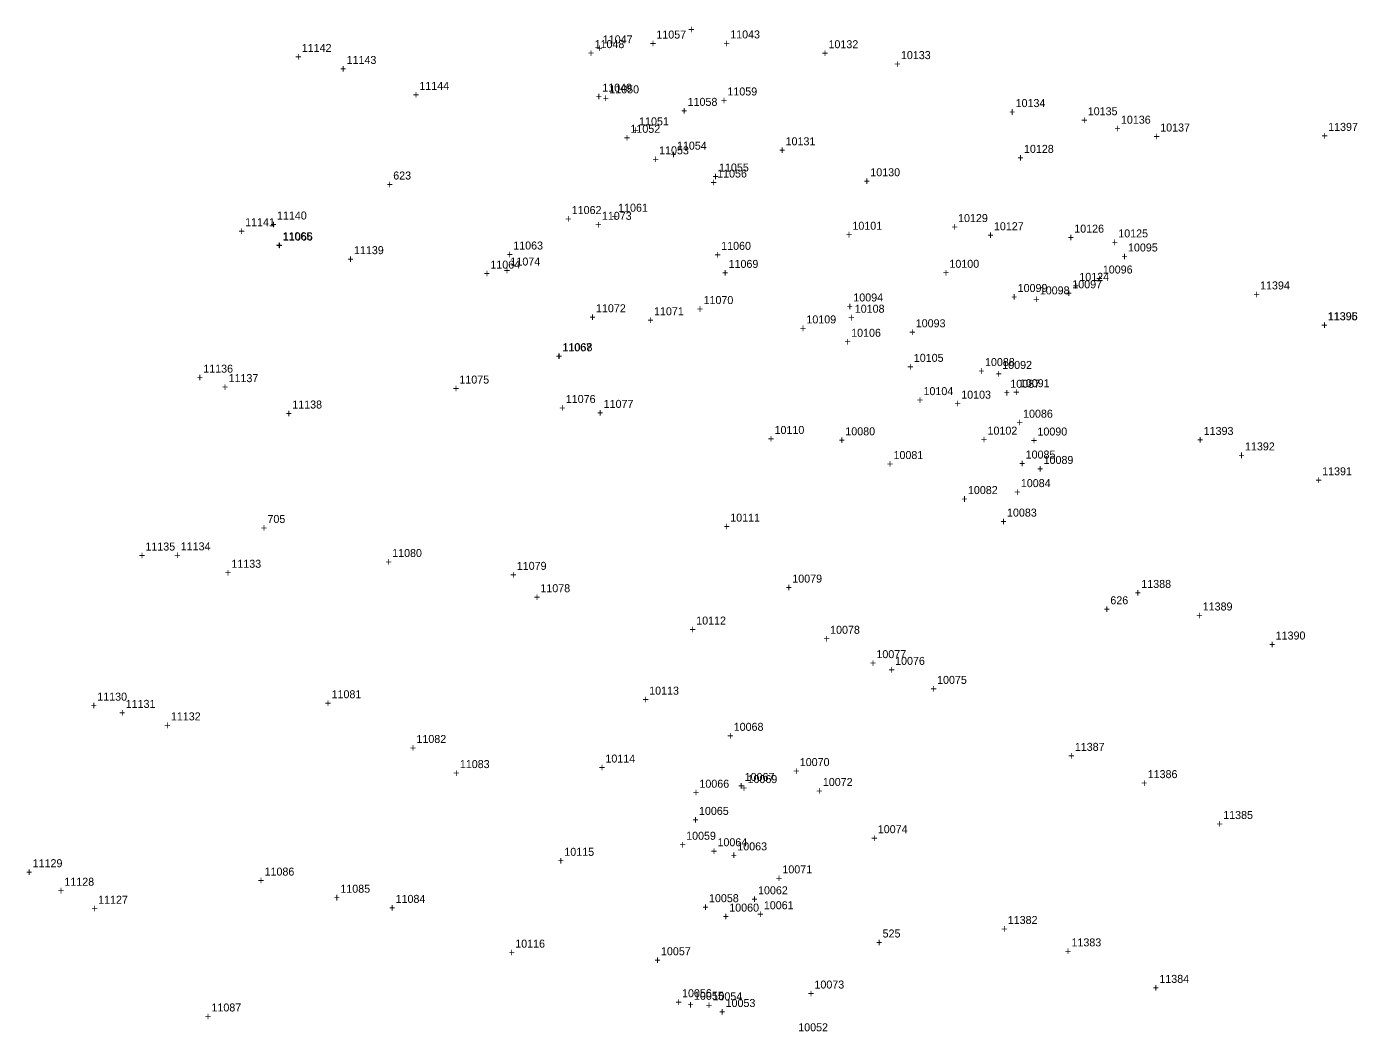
# Model space of a CAD drawing. Extents: x 1160051 to 1162814, y 614604 to 619560.
# Drawn here: x 1160136.8 to 1160552.5, y 615228.5 to 615542.6 of the extents above; entities that cross this region are included whole.
import ezdxf

# ---------------------------------------------------------------- set-up
doc = ezdxf.new("R2010")
doc.units = 0
for name, color, linetype in [('S_Control_Temp_Traverse', 7, 'Continuous'), ('S_Control_Traverse_Point', 7, 'Continuous'), ('S_Drainage_Culvert_Top', 7, 'Continuous'), ('S_Drainage_Invert', 7, 'Continuous'), ('S_Ground_Elevation', 7, 'Continuous'), ('S_Roadway_Drive_Paved', 7, 'Continuous'), ('S_Roadway_Monument', 7, 'Continuous'), ('S_Traffic_Sign_SinglePost', 7, 'Continuous'), ('S_Trees_TreeLine', 7, 'Continuous')]:
    doc.layers.add(name, color=color, linetype=linetype)

msp = doc.modelspace()

# ---------------------------------------------------------------- texts
at = {"layer": 'S_Control_Temp_Traverse'}
for s, p in [('623', (1160251.35, 615494.76)), ('+', (1160249.29, 615492.01)), ('626', (1160475.37, 615361.99)), ('+', (1160473.31, 615359.24)), ('525', (1160404.23, 615257.83)), ('+', (1160402.17, 615255.08))]:
    msp.add_text(s, height=2.5, dxfattribs=at).set_placement(p)
at = {"layer": 'S_Control_Traverse_Point'}
for s, p in [('+', (1160209.99, 615384.65)), ('+', (1160209.99, 615384.65)), ('+', (1160209.99, 615384.65)), ('+', (1160209.99, 615384.65)), ('705', (1160212.05, 615387.4)), ('705', (1160212.05, 615387.4)), ('705', (1160212.05, 615387.4)), ('705', (1160212.05, 615387.4))]:
    msp.add_text(s, height=2.5, dxfattribs=at).set_placement(p)
at = {"layer": 'S_Drainage_Culvert_Top'}
for s, p in [('11066', (1160216.92, 615475.66)), ('+', (1160214.86, 615472.91)), ('11067', (1160304.15, 615441.04)), ('+', (1160302.09, 615438.29))]:
    msp.add_text(s, height=2.5, dxfattribs=at).set_placement(p)
at = {"layer": 'S_Drainage_Invert'}
for s, p in [('11065', (1160216.77, 615475.79)), ('+', (1160214.71, 615473.04)), ('11068', (1160304.27, 615441.11)), ('+', (1160302.21, 615438.36))]:
    msp.add_text(s, height=2.5, dxfattribs=at).set_placement(p)
at = {"layer": 'S_Ground_Elevation'}
for s, p in [('+', (1160343.47, 615540.47)), ('11043', (1160356.62, 615538.87)), ('11142', (1160222.77, 615534.65)), ('+', (1160314.75, 615534.57)), ('11047', (1160316.81, 615537.32)), ('+', (1160354.56, 615536.12)), ('10132', (1160387.32, 615535.8)), ('+', (1160220.7, 615531.9)), ('11143', (1160236.78, 615530.89)), ('+', (1160385.25, 615533.05)), ('10133', (1160409.94, 615532.4)), ('+', (1160234.72, 615528.14)), ('+', (1160407.88, 615529.65)), ('11144', (1160259.52, 615522.79)), ('11050', (1160318.84, 615521.7)), ('+', (1160257.46, 615520.04)), ('+', (1160316.77, 615518.95)), ('11058', (1160343.31, 615517.79)), ('+', (1160353.68, 615518.29)), ('11059', (1160355.74, 615521.04)), ('10134', (1160445.78, 615517.41)), ('+', (1160341.25, 615515.04)), ('+', (1160443.72, 615514.66)), ('10135', (1160468.31, 615514.85)), ('11051', (1160328.16, 615511.7)), ('+', (1160466.24, 615512.1)), ('+', (1160476.61, 615509.46)), ('10136', (1160478.68, 615512.21)), ('10137', (1160490.95, 615509.77)), ('11397', (1160543.42, 615509.97)), ('+', (1160326.1, 615508.95)), ('10131', (1160373.92, 615505.46)), ('+', (1160488.89, 615507.02)), ('+', (1160541.36, 615507.22)), ('+', (1160337.92, 615501.35)), ('11054', (1160339.98, 615504.1)), ('+', (1160371.86, 615502.71)), ('11055', (1160353.12, 615497.27)), ('+', (1160351.06, 615494.52)), ('+', (1160398.33, 615493.03)), ('10130', (1160400.39, 615495.78)), ('11141', (1160205.09, 615480.17)), ('11140', (1160215.03, 615482.26)), ('11073', (1160316.53, 615482.17)), ('10129', (1160427.8, 615481.47)), ('+', (1160203.03, 615477.42)), ('+', (1160212.97, 615479.51)), ('+', (1160314.46, 615479.42)), ('+', (1160425.74, 615478.72)), ('+', (1160436.94, 615476.16)), ('10127', (1160439, 615478.91)), ('10126', (1160464.1, 615478.16)), ('10125', (1160477.85, 615476.67)), ('+', (1160462.04, 615475.41)), ('+', (1160475.78, 615473.92)), ('+', (1160237.03, 615468.68)), ('11139', (1160239.09, 615471.43)), ('11074', (1160287.97, 615467.88)), ('+', (1160285.91, 615465.13)), ('+', (1160354.05, 615464.39)), ('11069', (1160356.11, 615467.14)), ('+', (1160463.62, 615460.34)), ('10124', (1160465.68, 615463.09)), ('11394', (1160522.15, 615460.41)), ('11070', (1160348.29, 615455.83)), ('+', (1160520.09, 615457.66)), ('11072', (1160314.69, 615453.27)), ('11071', (1160332.82, 615452.33)), ('+', (1160346.22, 615453.08)), ('10108', (1160395.53, 615453.12)), ('11395', (1160543.28, 615450.78)), ('11396', (1160543.36, 615450.76)), ('+', (1160312.63, 615450.52)), ('+', (1160330.76, 615449.58)), ('+', (1160378.36, 615447.04)), ('10109', (1160380.42, 615449.79)), ('+', (1160393.47, 615450.37)), ('+', (1160541.22, 615448.03)), ('+', (1160541.3, 615448.01)), ('11136', (1160192, 615434.38)), ('+', (1160411.91, 615435.02)), ('10105', (1160413.97, 615437.77)), ('10088', (1160436.22, 615436.45)), ('+', (1160189.94, 615431.63)), ('11137', (1160199.9, 615431.43)), ('11075', (1160272.01, 615430.98)), ('+', (1160434.16, 615433.7)), ('+', (1160197.84, 615428.68)), ('+', (1160269.95, 615428.23)), ('10103', (1160428.78, 615426.25)), ('+', (1160442.06, 615426.91)), ('10087', (1160444.12, 615429.66)), ('11138', (1160219.81, 615423.18)), ('+', (1160303.18, 615422.16)), ('11076', (1160305.25, 615424.91)), ('11077', (1160317.08, 615423.38)), ('+', (1160426.72, 615423.5)), ('+', (1160217.75, 615420.43)), ('+', (1160315.02, 615420.63)), ('10086', (1160448.11, 615420.31)), ('10110', (1160370.47, 615415.23)), ('10080', (1160392.58, 615414.81)), ('10102', (1160437, 615415.01)), ('+', (1160446.05, 615417.56)), ('11393', (1160504.53, 615414.93)), ('+', (1160368.41, 615412.48)), ('+', (1160390.51, 615412.06)), ('+', (1160434.94, 615412.26)), ('+', (1160502.47, 615412.18)), ('11392', (1160517.44, 615410.09)), ('10085', (1160448.91, 615407.54)), ('+', (1160515.38, 615407.34)), ('+', (1160446.85, 615404.79)), ('11391', (1160541.54, 615402.31)), ('10084', (1160447.41, 615398.61)), ('+', (1160539.48, 615399.56)), ('+', (1160428.82, 615393.69)), ('10082', (1160430.88, 615396.44)), ('+', (1160445.35, 615395.86)), ('10083', (1160443.09, 615389.4)), ('+', (1160354.57, 615385.08)), ('10111', (1160356.63, 615387.83)), ('+', (1160441.03, 615386.65)), ('11135', (1160173.93, 615378.79)), ('11134', (1160184.96, 615378.85)), ('11080', (1160251.02, 615376.76)), ('+', (1160171.87, 615376.04)), ('+', (1160182.9, 615376.1)), ('11133', (1160200.79, 615373.4)), ('+', (1160248.96, 615374.01)), ('11079', (1160289.94, 615372.75)), ('+', (1160198.73, 615370.65)), ('+', (1160287.87, 615370)), ('10079', (1160376.01, 615368.76)), ('11078', (1160297.32, 615365.76)), ('+', (1160373.95, 615366.01)), ('+', (1160482.98, 615364.35)), ('11388', (1160485.05, 615367.1)), ('+', (1160295.26, 615363.01)), ('11389', (1160504.23, 615360.05)), ('10112', (1160345.99, 615355.65)), ('+', (1160502.17, 615357.3)), ('+', (1160343.93, 615352.9)), ('11390', (1160527.02, 615350.97)), ('+', (1160524.96, 615348.22)), ('10077', (1160402.29, 615345.15)), ('10076', (1160408.13, 615343.04)), ('+', (1160400.22, 615342.4)), ('+', (1160406.07, 615340.29)), ('10075', (1160421.24, 615337.11)), ('11130', (1160158.89, 615331.86)), ('11081', (1160232.08, 615332.62)), ('+', (1160329.24, 615330.99)), ('10113', (1160331.3, 615333.74)), ('+', (1160419.17, 615334.36)), ('+', (1160156.83, 615329.11)), ('+', (1160165.71, 615326.85)), ('11131', (1160167.77, 615329.6)), ('+', (1160230.01, 615329.87)), ('+', (1160179.83, 615322.94)), ('11132', (1160181.89, 615325.69)), ('10068', (1160357.71, 615322.43)), ('11082', (1160258.6, 615318.63)), ('+', (1160355.65, 615319.68)), ('+', (1160256.54, 615315.88)), ('11387', (1160464.27, 615316.17)), ('11083', (1160272.16, 615310.78)), ('10114', (1160317.63, 615312.51)), ('10070', (1160378.35, 615311.41)), ('+', (1160462.21, 615313.42)), ('+', (1160270.1, 615308.03)), ('+', (1160315.57, 615309.76)), ('10069', (1160362.02, 615306.09)), ('+', (1160376.28, 615308.66)), ('10072', (1160385.55, 615305.19)), ('11386', (1160487.04, 615307.64)), ('+', (1160344.94, 615301.9)), ('10066', (1160347, 615304.65)), ('+', (1160359.96, 615303.34)), ('+', (1160383.49, 615302.44)), ('+', (1160484.98, 615304.89)), ('+', (1160344.8, 615293.4)), ('10065', (1160346.86, 615296.15)), ('11385', (1160510.63, 615294.87)), ('10074', (1160402.72, 615290.44)), ('+', (1160508.57, 615292.12)), ('+', (1160340.79, 615285.63)), ('10059', (1160342.85, 615288.38)), ('10063', (1160358.83, 615285.06)), ('+', (1160400.66, 615287.69)), ('10115', (1160304.8, 615283.36)), ('+', (1160356.77, 615282.31)), ('+', (1160136.65, 615277.05)), ('11129', (1160138.71, 615279.8)), ('11086', (1160211.15, 615277.18)), ('+', (1160302.74, 615280.61)), ('10071', (1160372.92, 615277.88)), ('11128', (1160148.62, 615274.01)), ('+', (1160209.09, 615274.43)), ('+', (1160370.86, 615275.13)), ('+', (1160146.56, 615271.26)), ('11127', (1160159.16, 615268.39)), ('+', (1160232.76, 615269.07)), ('11085', (1160234.83, 615271.82)), ('11084', (1160252.09, 615268.65)), ('10058', (1160349.99, 615268.87)), ('+', (1160363.24, 615268.58)), ('10062', (1160365.31, 615271.33)), ('+', (1160157.09, 615265.64)), ('+', (1160250.03, 615265.9)), ('+', (1160347.93, 615266.12)), ('10060', (1160356.32, 615265.92)), ('10061', (1160367.12, 615266.66)), ('+', (1160354.26, 615263.17)), ('+', (1160365.06, 615263.91)), ('11382', (1160443.32, 615262.05)), ('+', (1160441.26, 615259.3)), ('+', (1160287.4, 615251.9)), ('10116', (1160289.46, 615254.65)), ('10057', (1160334.99, 615252.28)), ('+', (1160461.17, 615252.3)), ('11383', (1160463.23, 615255.05)), ('+', (1160332.93, 615249.53)), ('11384', (1160490.68, 615243.64)), ('10056', (1160341.57, 615239.16)), ('+', (1160380.87, 615239.12)), ('10073', (1160382.93, 615241.87)), ('+', (1160488.62, 615240.89)), ('11087', (1160194.56, 615234.7)), ('+', (1160339.51, 615236.41)), ('+', (1160349.02, 615235.43)), ('10054', (1160351.08, 615238.18)), ('10053', (1160355.18, 615236.11)), ('+', (1160192.49, 615231.95)), ('+', (1160353.12, 615233.36)), ('10052', (1160377.87, 615228.51))]:
    msp.add_text(s, height=2.5, dxfattribs=at).set_placement(p)
at = {"layer": 'S_Roadway_Drive_Paved'}
for s, p in [('11048', (1160314.24, 615535.83)), ('+', (1160312.18, 615533.08)), ('11049', (1160316.65, 615522.22)), ('+', (1160314.59, 615519.47)), ('11052', (1160325.45, 615509.36)), ('+', (1160323.38, 615506.61)), ('11053', (1160334.41, 615502.64)), ('+', (1160332.35, 615499.89)), ('11056', (1160352.54, 615495.39)), ('+', (1160350.48, 615492.64)), ('11062', (1160307.11, 615483.97)), ('11061', (1160321.6, 615484.7)), ('+', (1160305.05, 615481.22)), ('+', (1160319.54, 615481.95)), ('+', (1160392.73, 615476.32)), ('10101', (1160394.79, 615479.07)), ('11063', (1160288.84, 615472.88)), ('11060', (1160353.8, 615472.78)), ('10095', (1160480.88, 615472.27)), ('+', (1160286.78, 615470.13)), ('+', (1160351.74, 615470.03)), ('+', (1160478.82, 615469.52)), ('+', (1160279.63, 615464.16)), ('11064', (1160281.69, 615466.91)), ('+', (1160423.04, 615464.42)), ('10100', (1160425.1, 615467.17)), ('10096', (1160473.02, 615465.38)), ('10099', (1160446.42, 615459.6)), ('10097', (1160463.49, 615460.76)), ('+', (1160470.96, 615462.63)), ('10094', (1160395.08, 615456.65)), ('+', (1160444.36, 615456.85)), ('+', (1160451.27, 615456.11)), ('10098', (1160453.33, 615458.86)), ('+', (1160461.43, 615458.01)), ('+', (1160393.02, 615453.9)), ('10093', (1160414.58, 615448.57)), ('+', (1160412.52, 615445.82)), ('10092', (1160441.61, 615435.56)), ('+', (1160439.54, 615432.81)), ('+', (1160445.04, 615427.09)), ('10091', (1160447.1, 615429.84)), ('10090', (1160452.6, 615414.74)), ('+', (1160450.54, 615411.99)), ('10089', (1160454.52, 615405.86)), ('+', (1160452.46, 615403.11))]:
    msp.add_text(s, height=2.5, dxfattribs=at).set_placement(p)
at = {"layer": 'S_Roadway_Monument'}
for s, p in [('10128', (1160448.39, 615503.09)), ('+', (1160446.33, 615500.34))]:
    msp.add_text(s, height=2.5, dxfattribs=at).set_placement(p)
at = {"layer": 'S_Traffic_Sign_SinglePost'}
for s, p in [('11057', (1160333.55, 615538.82)), ('+', (1160331.49, 615536.07))]:
    msp.add_text(s, height=2.5, dxfattribs=at).set_placement(p)
at = {"layer": 'S_Trees_TreeLine'}
for s, p in [('+', (1160392.34, 615442.85)), ('10106', (1160394.4, 615445.6)), ('10104', (1160417, 615427.37)), ('+', (1160414.94, 615424.63)), ('10081', (1160407.63, 615407.39)), ('+', (1160405.57, 615404.64)), ('10078', (1160387.83, 615352.76)), ('+', (1160385.77, 615350.01)), ('10067', (1160361.13, 615306.77)), ('+', (1160359.07, 615304.02)), ('10064', (1160352.64, 615286.35)), ('+', (1160350.58, 615283.6)), ('+', (1160343.24, 615235.6)), ('10055', (1160345.3, 615238.35))]:
    msp.add_text(s, height=2.5, dxfattribs=at).set_placement(p)

doc.saveas('drawing.dxf')
